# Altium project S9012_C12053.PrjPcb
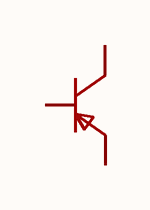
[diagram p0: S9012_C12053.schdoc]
1 sheet, 1 parts. Net scope: global (net labels, ports and power ports of the same name join across sheets).

## Sheet S9012_C12053.schdoc
size 127 x 101 mm

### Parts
Q?  s9012(range:144-202)  [TO-92-3_L5.1-W4.1-P1.27-L]  (value not drawn)

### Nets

Not connected (* = marked no-connect by the designer): Q? 1(E) 2(B) 3(C)

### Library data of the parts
Q? = s9012(range:144-202): 晶体管类型:PNP;集电极电流(Ic):500mA;集射极击穿电压(Vceo):25V;耗散功率(Pd):625mW;直流电流增益(hFE):144;; Manufacturer: CJ(江苏长电/长晶); Symbol: S9012_C12053; AddInBom: yes; ModelId: db569d051dcd4484acf2f9e50678fca3; ModelName: TO-92-3_L4.9-W3.7-P1.27-L; ModelTransform: 180.7872,141.4455,0,0,0,0,0,19.252,-196.85; type: PNP; Current - Collector(Ic): 500mA; Collector - Emitter Voltage VCEO: 25V; Pd - Power Dissipation: 625mW; DC Current Gain: 144; Transition frequency(fT): 150MHz; Current - Collector Cutoff: 100nA; Vce Saturation(VCE(sat)): 600mV; Emitter-Base Voltage(Vebo): 5V; Number: 1个PNP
